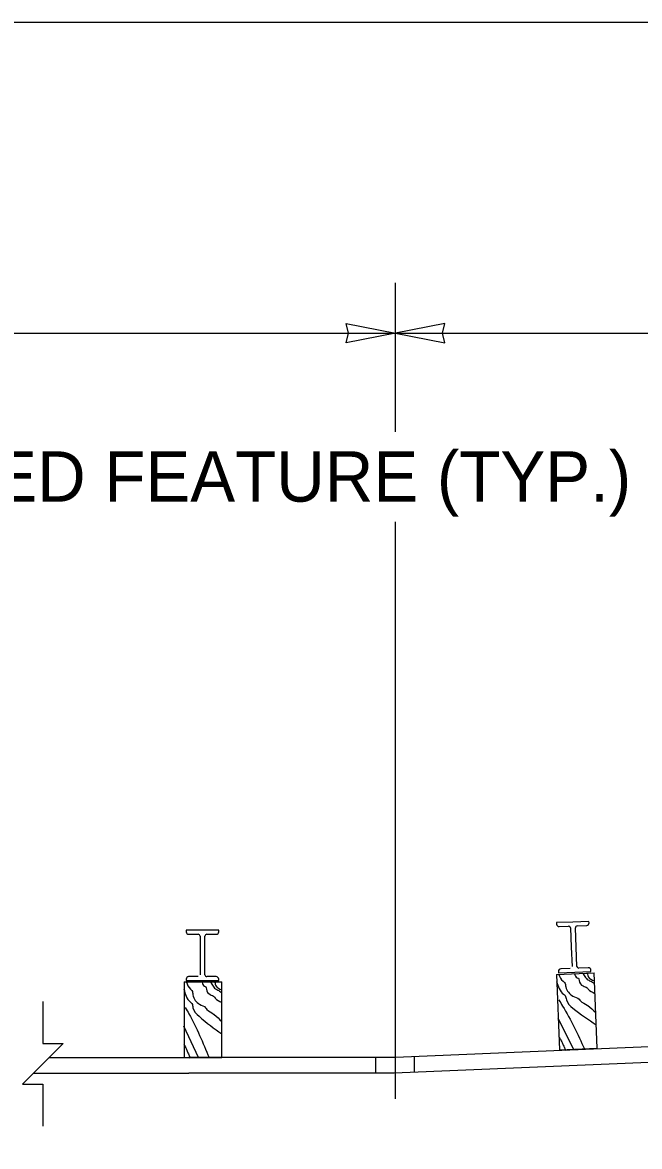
# Model space of a CAD drawing. Extents: x 99862 to 103680, y 99470 to 102076.
# Drawn here: x 102003.8 to 102200.1, y 101718.1 to 102075.5 of the extents above; entities that cross this region are included whole.
import ezdxf

# ---------------------------------------------------------------- set-up
doc = ezdxf.new("R2010")
doc.units = 0
for name, color, linetype in [('Level 1', 7, 'Continuous'), ('Level 10', 7, 'Continuous'), ('Level 11', 7, 'Continuous'), ('Level 13', 7, 'Continuous'), ('Level 15', 7, 'Continuous'), ('Level 18', 7, 'Continuous'), ('Level 20', 7, 'Continuous'), ('Level 9', 7, 'Continuous')]:
    doc.layers.add(name, color=color, linetype=linetype)

msp = doc.modelspace()

# ---------------------------------------------------------------- linework, layer by layer
at = {"layer": 'Level 1'}
for p, q in [((102012.29, 101746.44), (102056.72, 101746.44)), ((102007.3, 101741.46), (102056.72, 101741.46))]:
    msp.add_line(p, q, dxfattribs=at)
msp.add_lwpolyline([(99862, 99999.5), (103151, 99999.5), (103151, 102075.5), (99862, 102075.5)], close=True, dxfattribs=at)
at = {"layer": 'Level 10'}
for p, q in [((102173.67, 101772.85), (102185.66, 101773.34)), ((102173.67, 101772.85), (102185.66, 101773.34)), ((102173.67, 101772.85), (102185.66, 101773.34)), ((102173.67, 101772.85), (102185.66, 101773.34)), ((102173.67, 101772.85), (102174.66, 101748.87)), ((102173.67, 101772.85), (102174.66, 101748.87)), ((102173.67, 101772.85), (102174.66, 101748.87)), ((102173.67, 101772.85), (102174.66, 101748.87)), ((102186.65, 101749.36), (102185.66, 101773.34)), ((102186.65, 101749.36), (102185.66, 101773.34)), ((102186.65, 101749.36), (102185.66, 101773.34)), ((102186.65, 101749.36), (102185.66, 101773.34)), ((102055.22, 101770.44), (102067.22, 101770.44)), ((102055.22, 101770.44), (102055.22, 101746.44)), ((102067.22, 101746.44), (102067.22, 101770.44)), ((102174.66, 101748.87), (102186.65, 101749.36)), ((102174.66, 101748.87), (102186.65, 101749.36)), ((102174.66, 101748.87), (102186.65, 101749.36)), ((102174.66, 101748.87), (102186.65, 101749.36)), ((102179.72, 101749), (102179.71, 101749.08)), ((102179.72, 101749), (102179.71, 101749.08)), ((102179.72, 101749), (102179.71, 101749.08)), ((102179.72, 101749), (102179.71, 101749.08)), ((102179.72, 101749), (102179.71, 101749.08)), ((102179.72, 101749), (102179.71, 101749.08)), ((102179.72, 101749), (102179.71, 101749.08)), ((102179.72, 101749), (102179.71, 101749.08)), ((102181.59, 101749.15), (102181.59, 101749.07)), ((102181.59, 101749.15), (102181.59, 101749.07)), ((102181.59, 101749.15), (102181.59, 101749.07)), ((102181.59, 101749.15), (102181.59, 101749.07)), ((102181.59, 101749.15), (102181.59, 101749.07)), ((102181.59, 101749.15), (102181.59, 101749.07)), ((102181.59, 101749.15), (102181.59, 101749.07)), ((102181.59, 101749.15), (102181.59, 101749.07)), ((102055.22, 101746.44), (102067.22, 101746.44)), ((102060.28, 101746.36), (102060.28, 101746.44)), ((102060.28, 101746.36), (102060.28, 101746.44)), ((102062.15, 101746.44), (102062.15, 101746.36)), ((102062.15, 101746.44), (102062.15, 101746.36))]:
    msp.add_line(p, q, dxfattribs=at)
at = {"layer": 'Level 11'}
for p, q in [((102116.08, 101746.34), (102116.08, 101741.46)), ((102128.39, 101746.71), (102128.39, 101741.75))]:
    msp.add_line(p, q, dxfattribs=at)
at = {"layer": 'Level 13'}
for p, q in [((102174.12, 101758.95), (102179.12, 101749.13)), ((102174.12, 101758.95), (102179.12, 101749.13)), ((102174.12, 101758.95), (102179.12, 101749.13)), ((102174.12, 101758.95), (102179.12, 101749.13)), ((102055.09, 101756.53), (102059.69, 101746.52))]:
    msp.add_line(p, q, dxfattribs=at)
for points in [[(102174.43, 101772.87), (102175.79, 101770.65), (102176.26, 101770.26), (102176.68, 101768.89), (102178.92, 101765.96), (102180.87, 101764.94), (102181.31, 101764.42), (102183.5, 101763.06), (102183.68, 101762.93), (102186.19, 101760.74)], [(102174.43, 101772.87), (102175.79, 101770.65), (102176.26, 101770.26), (102176.68, 101768.89), (102178.92, 101765.96), (102180.87, 101764.94), (102181.31, 101764.42), (102183.5, 101763.06), (102183.68, 101762.93), (102186.19, 101760.74)], [(102174.43, 101772.87), (102175.79, 101770.65), (102176.26, 101770.26), (102176.68, 101768.89), (102178.92, 101765.96), (102180.87, 101764.94), (102181.31, 101764.42), (102183.5, 101763.06), (102183.68, 101762.93), (102186.19, 101760.74)], [(102174.43, 101772.87), (102175.79, 101770.65), (102176.26, 101770.26), (102176.68, 101768.89), (102178.92, 101765.96), (102180.87, 101764.94), (102181.31, 101764.42), (102183.5, 101763.06), (102183.68, 101762.93), (102186.19, 101760.74)], [(102179.4, 101773.08), (102180.27, 101771.76), (102180.67, 101771.61), (102180.87, 101770.9), (102182.18, 101769.18), (102183.44, 101768.58), (102183.79, 101768.15), (102185.91, 101766.83)], [(102179.4, 101773.08), (102180.27, 101771.76), (102180.67, 101771.61), (102180.87, 101770.9), (102182.18, 101769.18), (102183.44, 101768.58), (102183.79, 101768.15), (102185.91, 101766.83)], [(102179.4, 101773.08), (102180.27, 101771.76), (102180.67, 101771.61), (102180.87, 101770.9), (102182.18, 101769.18), (102183.44, 101768.58), (102183.79, 101768.15), (102185.91, 101766.83)], [(102179.4, 101773.08), (102180.27, 101771.76), (102180.67, 101771.61), (102180.87, 101770.9), (102182.18, 101769.18), (102183.44, 101768.58), (102183.79, 101768.15), (102185.91, 101766.83)], [(102182.09, 101773.2), (102182.53, 101772.53), (102183.49, 101771.28), (102184.5, 101770.73), (102185.7, 101770.04)], [(102182.09, 101773.2), (102182.53, 101772.53), (102183.49, 101771.28), (102184.5, 101770.73), (102185.7, 101770.04)], [(102182.09, 101773.2), (102182.53, 101772.53), (102183.49, 101771.28), (102184.5, 101770.73), (102185.7, 101770.04)], [(102182.09, 101773.2), (102182.53, 101772.53), (102183.49, 101771.28), (102184.5, 101770.73), (102185.7, 101770.04)], [(102183.5, 101773.23), (102183.91, 101771.92), (102185.66, 101770.87)], [(102183.5, 101773.23), (102183.91, 101771.92), (102185.66, 101770.87)], [(102183.5, 101773.23), (102183.91, 101771.92), (102185.66, 101770.87)], [(102183.5, 101773.23), (102183.91, 101771.92), (102185.66, 101770.87)], [(102055.97, 101770.43), (102057.25, 101768.16), (102057.7, 101767.75), (102058.05, 101766.36), (102060.18, 101763.34), (102062.09, 101762.25), (102062.5, 101761.71), (102064.63, 101760.25), (102064.81, 101760.12), (102067.23, 101757.83)], [(102060.94, 101770.43), (102061.76, 101769.08), (102062.16, 101768.92), (102062.32, 101768.2), (102063.57, 101766.43), (102064.81, 101765.77), (102065.13, 101765.34), (102067.19, 101763.93)], [(102063.64, 101770.45), (102064.05, 101769.76), (102064.96, 101768.47), (102065.95, 101767.88), (102067.12, 101767.14)], [(102065.05, 101770.42), (102065.41, 101769.1), (102067.11, 101767.97)], [(102173.71, 101770.58), (102175.97, 101766.53), (102176.44, 101766.14), (102176.85, 101764.77), (102178.91, 101762.13), (102186.34, 101756.84)], [(102173.71, 101770.58), (102175.97, 101766.53), (102176.44, 101766.14), (102176.85, 101764.77), (102178.91, 101762.13), (102186.34, 101756.84)], [(102173.71, 101770.58), (102175.97, 101766.53), (102176.44, 101766.14), (102176.85, 101764.77), (102178.91, 101762.13), (102186.34, 101756.84)], [(102173.71, 101770.58), (102175.97, 101766.53), (102176.44, 101766.14), (102176.85, 101764.77), (102178.91, 101762.13), (102186.34, 101756.84)], [(102055.16, 101768.18), (102057.25, 101764.03), (102057.71, 101763.63), (102058.06, 101762.24), (102060.01, 101759.52), (102067.21, 101753.93)], [(102055.62, 101762.32), (102056.77, 101760.31), (102063.18, 101746.38)], [(102174.41, 101764.75), (102175.64, 101762.78), (102182.62, 101749.14)], [(102174.41, 101764.75), (102175.64, 101762.78), (102182.62, 101749.14)], [(102174.41, 101764.75), (102175.64, 101762.78), (102182.62, 101749.14)], [(102174.41, 101764.75), (102175.64, 101762.78), (102182.62, 101749.14)], [(102174.47, 101753.03), (102174.63, 101752.78), (102174.78, 101752.52), (102175.08, 101751.99), (102175.61, 101750.9), (102176.11, 101749.79), (102176.37, 101749.24), (102176.63, 101748.69)], [(102174.47, 101753.03), (102174.63, 101752.78), (102174.78, 101752.52), (102175.08, 101751.99), (102175.61, 101750.9), (102176.11, 101749.79), (102176.37, 101749.24), (102176.63, 101748.69)], [(102174.47, 101753.03), (102174.63, 101752.78), (102174.78, 101752.52), (102175.08, 101751.99), (102175.61, 101750.9), (102176.11, 101749.79), (102176.37, 101749.24), (102176.63, 101748.69)], [(102174.47, 101753.03), (102174.63, 101752.78), (102174.78, 101752.52), (102175.08, 101751.99), (102175.61, 101750.9), (102176.11, 101749.79), (102176.37, 101749.24), (102176.63, 101748.69)], [(102055.2, 101750.61), (102055.35, 101750.35), (102055.49, 101750.08), (102055.77, 101749.55), (102056.25, 101748.43), (102056.71, 101747.3), (102056.94, 101746.74), (102057.18, 101746.18)]]:
    msp.add_spline(points, degree=3, dxfattribs=at)
at = {"layer": 'Level 15'}
for p, q in [((102122.49, 101945.34), (102122.49, 101992.73)), ((101443.89, 101976.73), (102122.49, 101976.73)), ((102122.49, 101976.73), (102995.35, 101976.73)), ((102122.49, 101733.33), (102122.49, 101916.74))]:
    msp.add_line(p, q, dxfattribs=at)
for points in [[(102122.49, 101976.73), (102106.76, 101973.64), (102107.49, 101976.73), (102106.76, 101979.81)], [(102122.49, 101976.73), (102138.21, 101973.64), (102137.49, 101976.73), (102138.21, 101979.81)]]:
    msp.add_lwpolyline(points, close=True, dxfattribs=at)
msp.add_lwpolyline([(102010.27, 101764.21), (102010.27, 101750.88), (102016.73, 101750.88), (102003.82, 101737.98), (102010.27, 101737.98), (102010.27, 101724.64)], dxfattribs=at)
at = {"layer": 'Level 18'}
for p, q in [((102564.82, 101759.93), (102122.04, 101741.46)), ((102400.88, 101758.08), (102122.49, 101746.47)), ((102122.49, 101746.44), (102056.72, 101746.44)), ((102122.04, 101741.46), (102056.72, 101741.46))]:
    msp.add_line(p, q, dxfattribs=at)
at = {"layer": 'Level 20'}
msp.add_line((102180.57, 101748.89), (102180.65, 101749.12), dxfattribs=at)
at = {"layer": 'Level 9'}
for p, q in [((102178.17, 101787.62), (102178.42, 101781.48)), ((102178.17, 101787.62), (102178.42, 101781.48)), ((102178.17, 101787.62), (102178.42, 101781.48)), ((102178.17, 101787.62), (102178.42, 101781.48)), ((102179.96, 101781.55), (102179.71, 101787.68)), ((102179.96, 101781.55), (102179.71, 101787.68)), ((102179.96, 101781.55), (102179.71, 101787.68)), ((102179.96, 101781.55), (102179.71, 101787.68)), ((102060.32, 101785.01), (102060.31, 101778.88)), ((102061.85, 101778.87), (102061.86, 101785.01)), ((102178.42, 101781.48), (102178.66, 101775.35)), ((102178.42, 101781.48), (102178.66, 101775.35)), ((102178.42, 101781.48), (102178.66, 101775.35)), ((102178.42, 101781.48), (102178.66, 101775.35)), ((102180.2, 101775.41), (102179.96, 101781.55)), ((102180.2, 101775.41), (102179.96, 101781.55)), ((102180.2, 101775.41), (102179.96, 101781.55)), ((102180.2, 101775.41), (102179.96, 101781.55)), ((102060.31, 101778.88), (102060.3, 101772.74)), ((102061.84, 101772.74), (102061.85, 101778.87))]:
    msp.add_line(p, q, dxfattribs=at)
for points in [[(102061.09, 101786.87), (102055.92, 101786.88), (102055.92, 101786.4)], [(102066.26, 101786.38), (102066.26, 101786.87), (102061.09, 101786.87)], [(102178.87, 101789.51), (102173.7, 101789.3), (102173.72, 101788.82)], [(102178.87, 101789.51), (102173.7, 101789.3), (102173.72, 101788.82)], [(102178.87, 101789.51), (102173.7, 101789.3), (102173.72, 101788.82)], [(102178.87, 101789.51), (102173.7, 101789.3), (102173.72, 101788.82)], [(102174.54, 101788.06), (102177.56, 101788.18)], [(102174.54, 101788.06), (102177.56, 101788.18)], [(102174.54, 101788.06), (102177.56, 101788.18)], [(102174.54, 101788.06), (102177.56, 101788.18)], [(102184.05, 101789.23), (102184.03, 101789.71), (102178.87, 101789.51)], [(102184.05, 101789.23), (102184.03, 101789.71), (102178.87, 101789.51)], [(102184.05, 101789.23), (102184.03, 101789.71), (102178.87, 101789.51)], [(102184.05, 101789.23), (102184.03, 101789.71), (102178.87, 101789.51)], [(102180.28, 101788.29), (102183.3, 101788.41)], [(102180.28, 101788.29), (102183.3, 101788.41)], [(102180.28, 101788.29), (102183.3, 101788.41)], [(102180.28, 101788.29), (102183.3, 101788.41)], [(102056.71, 101785.61), (102059.73, 101785.6)], [(102062.45, 101785.6), (102065.47, 101785.6)], [(102174.32, 101773.8), (102174.34, 101773.32), (102179.5, 101773.52)], [(102174.32, 101773.8), (102174.34, 101773.32), (102179.5, 101773.52)], [(102174.32, 101773.8), (102174.34, 101773.32), (102179.5, 101773.52)], [(102174.32, 101773.8), (102174.34, 101773.32), (102179.5, 101773.52)], [(102178.09, 101774.74), (102175.08, 101774.62)], [(102178.09, 101774.74), (102175.08, 101774.62)], [(102178.09, 101774.74), (102175.08, 101774.62)], [(102178.09, 101774.74), (102175.08, 101774.62)], [(102179.5, 101773.52), (102184.67, 101773.73), (102184.65, 101774.21)], [(102179.5, 101773.52), (102184.67, 101773.73), (102184.65, 101774.21)], [(102179.5, 101773.52), (102184.67, 101773.73), (102184.65, 101774.21)], [(102179.5, 101773.52), (102184.67, 101773.73), (102184.65, 101774.21)], [(102183.83, 101774.97), (102180.81, 101774.85)], [(102183.83, 101774.97), (102180.81, 101774.85)], [(102183.83, 101774.97), (102180.81, 101774.85)], [(102183.83, 101774.97), (102180.81, 101774.85)], [(102055.9, 101771.36), (102055.9, 101770.88), (102061.07, 101770.87)], [(102059.71, 101772.15), (102056.69, 101772.15)], [(102061.07, 101770.87), (102066.24, 101770.87), (102066.24, 101771.35)], [(102065.45, 101772.14), (102062.43, 101772.14)]]:
    msp.add_lwpolyline(points, dxfattribs=at)
for centre, radius, start, end in [((102174.51, 101788.85), 0.788, 182.2775, 272.2775), ((102174.51, 101788.85), 0.788, 182.2775, 272.2775), ((102174.51, 101788.85), 0.788, 182.2775, 272.2775), ((102174.51, 101788.85), 0.788, 182.2775, 272.2775), ((102177.58, 101787.59), 0.591, 2.2775, 92.2775), ((102177.58, 101787.59), 0.591, 2.2775, 92.2775), ((102177.58, 101787.59), 0.591, 2.2775, 92.2775), ((102177.58, 101787.59), 0.591, 2.2775, 92.2775), ((102180.3, 101787.7), 0.591, 92.2775, 182.2775), ((102180.3, 101787.7), 0.591, 92.2775, 182.2775), ((102180.3, 101787.7), 0.591, 92.2775, 182.2775), ((102180.3, 101787.7), 0.591, 92.2775, 182.2775), ((102183.27, 101789.2), 0.788, 272.2775, 2.2775), ((102183.27, 101789.2), 0.788, 272.2775, 2.2775), ((102183.27, 101789.2), 0.788, 272.2775, 2.2775), ((102183.27, 101789.2), 0.788, 272.2775, 2.2775), ((102056.71, 101786.4), 0.788, 179.9273, 269.9273), ((102059.73, 101785.01), 0.591, 359.9273, 89.9273), ((102062.45, 101785.01), 0.591, 89.9273, 179.9273), ((102065.47, 101786.38), 0.788, 269.9273, 359.9273), ((102062.44, 101772.74), 0.591, 179.9273, 269.9273), ((102175.11, 101773.83), 0.788, 92.2775, 182.2979), ((102175.11, 101773.83), 0.788, 92.2775, 182.2979), ((102175.11, 101773.83), 0.788, 92.2775, 182.2979), ((102175.11, 101773.83), 0.788, 92.2775, 182.2979), ((102180.79, 101775.44), 0.591, 182.2775, 272.2775), ((102180.79, 101775.44), 0.591, 182.2775, 272.2775), ((102180.79, 101775.44), 0.591, 182.2775, 272.2775), ((102180.79, 101775.44), 0.591, 182.2775, 272.2775), ((102183.86, 101774.18), 0.788, 2.2979, 92.2775), ((102183.86, 101774.18), 0.788, 2.2979, 92.2775), ((102183.86, 101774.18), 0.788, 2.2979, 92.2775), ((102183.86, 101774.18), 0.788, 2.2979, 92.2775), ((102056.69, 101771.36), 0.788, 89.9273, 179.9478), ((102065.45, 101771.35), 0.788, 359.9478, 89.9273)]:
    msp.add_arc(centre, radius, start, end, dxfattribs=at)

# ---------------------------------------------------------------- texts
at = {"layer": 'Level 20'}
msp.add_text('FIXED FEATURE (TYP.)', height=16, rotation=360, dxfattribs=at).set_placement((101960.91, 101923.15))

doc.saveas('drawing.dxf')
